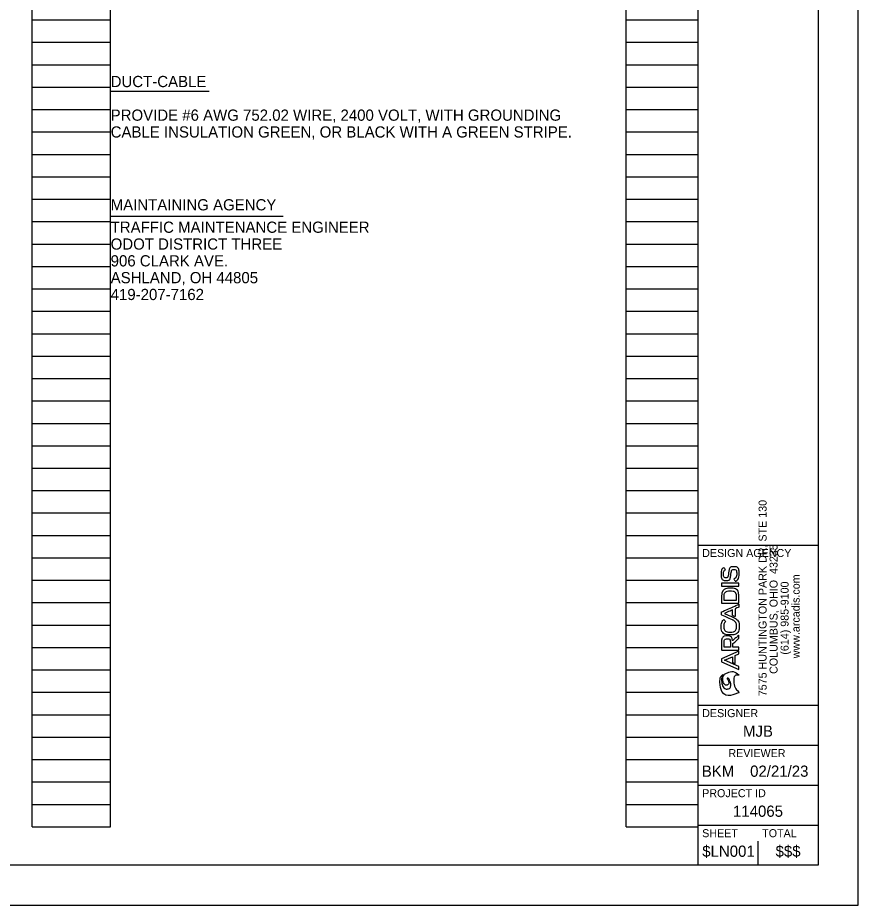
# Model space of a CAD drawing. Extents: x 0 to 59.1, y 0 to 22.
# Drawn here: x 23.5 to 34, y 0 to 11.09 of the extents above; entities that cross this region are included whole.
import ezdxf

# ---------------------------------------------------------------- set-up
doc = ezdxf.new("R2010")
doc.units = 0
for name, color, linetype in [('SH_Border', 7, 'Continuous'), ('SH_Cut_Line', 7, 'Continuous'), ('SH_Data', 7, 'Continuous'), ('SH_Text', 7, 'Continuous')]:
    doc.layers.add(name, color=color, linetype=linetype)

msp = doc.modelspace()

# ---------------------------------------------------------------- linework, layer by layer
at = {"layer": 'SH_Border'}
for p, q in [((32, 0.5), (32, 21.5)), ((32, 4.5), (33.5, 4.5)), ((32, 2.5), (33.5, 2.5)), ((32, 2), (33.5, 2)), ((32, 1.5), (33.5, 1.5)), ((32, 1), (33.5, 1))]:
    msp.add_line(p, q, dxfattribs=at)
msp.add_lwpolyline([(1.5, 21.5), (33.5, 21.5), (33.5, 0.5), (1.5, 0.5)], close=True, dxfattribs=at)
at = {"layer": 'SH_Cut_Line'}
msp.add_lwpolyline([(0, 0), (34, 0), (34, 22), (0, 22)], close=True, dxfattribs=at)
at = {"layer": 'SH_Data'}
for p, q in [((23.68, 0.98), (23.68, 21.14)), ((24.66, 0.98), (24.66, 21.14)), ((31.1, 0.98), (31.1, 21.14)), ((32, 0.98), (32, 21.14)), ((23.68, 11.06), (24.66, 11.06)), ((31.1, 11.06), (32, 11.06)), ((23.68, 10.78), (24.66, 10.78)), ((31.1, 10.78), (32, 10.78)), ((23.68, 10.5), (24.66, 10.5)), ((31.1, 10.5), (32, 10.5)), ((23.68, 10.22), (24.66, 10.22)), ((31.1, 10.22), (32, 10.22)), ((23.68, 9.94), (24.66, 9.94)), ((31.1, 9.94), (32, 9.94)), ((23.68, 9.66), (24.66, 9.66)), ((31.1, 9.66), (32, 9.66)), ((23.68, 9.38), (24.66, 9.38)), ((31.1, 9.38), (32, 9.38)), ((23.68, 9.1), (24.66, 9.1)), ((31.1, 9.1), (32, 9.1)), ((23.68, 8.82), (24.66, 8.82)), ((31.1, 8.82), (32, 8.82)), ((23.68, 8.54), (24.66, 8.54)), ((31.1, 8.54), (32, 8.54)), ((23.68, 8.26), (24.66, 8.26)), ((31.1, 8.26), (32, 8.26)), ((23.68, 7.98), (24.66, 7.98)), ((31.1, 7.98), (32, 7.98)), ((23.68, 7.7), (24.66, 7.7)), ((31.1, 7.7), (32, 7.7)), ((23.68, 7.42), (24.66, 7.42)), ((31.1, 7.42), (32, 7.42)), ((23.68, 7.14), (24.66, 7.14)), ((31.1, 7.14), (32, 7.14)), ((23.68, 6.86), (24.66, 6.86)), ((31.1, 6.86), (32, 6.86)), ((23.68, 6.58), (24.66, 6.58)), ((31.1, 6.58), (32, 6.58)), ((23.68, 6.3), (24.66, 6.3)), ((31.1, 6.3), (32, 6.3)), ((23.68, 6.02), (24.66, 6.02)), ((31.1, 6.02), (32, 6.02)), ((23.68, 5.74), (24.66, 5.74)), ((31.1, 5.74), (32, 5.74)), ((23.68, 5.46), (24.66, 5.46)), ((31.1, 5.46), (32, 5.46)), ((23.68, 5.18), (24.66, 5.18)), ((31.1, 5.18), (32, 5.18)), ((23.68, 4.9), (24.66, 4.9)), ((31.1, 4.9), (32, 4.9)), ((23.68, 4.62), (24.66, 4.62)), ((31.1, 4.62), (32, 4.62)), ((23.68, 4.34), (24.66, 4.34)), ((31.1, 4.34), (32, 4.34)), ((23.68, 4.06), (24.66, 4.06)), ((31.1, 4.06), (32, 4.06)), ((32.507, 4.022), (32.292, 4.022)), ((32.292, 4.022), (32.292, 3.988)), ((32.507, 4.022), (32.292, 4.022)), ((32.292, 4.022), (32.292, 3.988)), ((32.507, 4.022), (32.292, 4.022)), ((32.292, 4.022), (32.292, 3.988)), ((32.507, 3.988), (32.507, 4.022)), ((32.507, 3.988), (32.507, 4.022)), ((32.507, 3.988), (32.507, 4.022)), ((32.292, 3.988), (32.507, 3.988)), ((32.292, 3.988), (32.507, 3.988)), ((32.292, 3.988), (32.507, 3.988)), ((23.68, 3.78), (24.66, 3.78)), ((31.1, 3.78), (32, 3.78)), ((23.68, 3.5), (24.66, 3.5)), ((31.1, 3.5), (32, 3.5)), ((32.75, 3.5), (32.75, 3.5)), ((32.75, 3.5), (32.75, 3.5)), ((32.75, 3.5), (32.75, 3.5)), ((32.75, 3.5), (32.75, 3.5)), ((23.68, 3.22), (24.66, 3.22)), ((31.1, 3.22), (32, 3.22)), ((32.507, 3.175), (32.292, 3.079)), ((32.507, 3.175), (32.292, 3.079)), ((32.507, 3.175), (32.292, 3.079)), ((32.328, 3.06), (32.431, 3.105)), ((32.328, 3.06), (32.431, 3.105)), ((32.328, 3.06), (32.431, 3.105)), ((32.431, 3.105), (32.431, 3.034)), ((32.431, 3.105), (32.431, 3.034)), ((32.431, 3.105), (32.431, 3.034)), ((32.462, 3.119), (32.507, 3.139)), ((32.462, 3.119), (32.507, 3.139)), ((32.462, 3.119), (32.507, 3.139)), ((32.462, 3.02), (32.462, 3.119)), ((32.462, 3.02), (32.462, 3.119)), ((32.462, 3.02), (32.462, 3.119)), ((32.507, 3.139), (32.507, 3.175)), ((32.507, 3.139), (32.507, 3.175)), ((32.507, 3.139), (32.507, 3.175)), ((32.292, 3.079), (32.292, 3.041)), ((32.292, 3.079), (32.292, 3.041)), ((32.292, 3.079), (32.292, 3.041)), ((32.292, 3.041), (32.507, 2.945)), ((32.292, 3.041), (32.507, 2.945)), ((32.292, 3.041), (32.507, 2.945)), ((32.507, 2.981), (32.328, 3.06)), ((32.507, 2.981), (32.328, 3.06)), ((32.507, 2.981), (32.328, 3.06)), ((32.431, 3.034), (32.462, 3.02)), ((32.431, 3.034), (32.462, 3.02)), ((32.431, 3.034), (32.462, 3.02)), ((23.68, 2.94), (24.66, 2.94)), ((31.1, 2.94), (32, 2.94)), ((32.507, 2.945), (32.507, 2.981)), ((32.507, 2.945), (32.507, 2.981)), ((32.507, 2.945), (32.507, 2.981)), ((23.68, 2.66), (24.66, 2.66)), ((31.1, 2.66), (32, 2.66)), ((23.68, 2.38), (24.66, 2.38)), ((31.1, 2.38), (32, 2.38)), ((23.68, 2.1), (24.66, 2.1)), ((31.1, 2.1), (32, 2.1)), ((23.68, 1.82), (24.66, 1.82)), ((31.1, 1.82), (32, 1.82)), ((23.68, 1.54), (24.66, 1.54)), ((31.1, 1.54), (32, 1.54)), ((23.68, 1.26), (24.66, 1.26)), ((31.1, 1.26), (32, 1.26)), ((23.68, 0.98), (24.66, 0.98)), ((31.1, 0.98), (32, 0.98)), ((32.75, 0.5), (32.75, 0.8)), ((32.375, 0.675), (32.375, 0.675))]:
    msp.add_line(p, q, dxfattribs=at)
for points, degree in [([(32.34, 4.193), (32.325, 4.183), (32.316, 4.163), (32.316, 4.14), (32.316, 4.111), (32.328, 4.09), (32.348, 4.09), (32.369, 4.09), (32.375, 4.114), (32.379, 4.143), (32.385, 4.187), (32.398, 4.229), (32.446, 4.229), (32.494, 4.229), (32.512, 4.185), (32.512, 4.14), (32.512, 4.099), (32.5, 4.067), (32.463, 4.047), (32.463, 4.047), (32.446, 4.073), (32.446, 4.073), (32.472, 4.088), (32.482, 4.115), (32.482, 4.14), (32.482, 4.166), (32.473, 4.195), (32.446, 4.195), (32.422, 4.195), (32.414, 4.17), (32.41, 4.14), (32.405, 4.097), (32.394, 4.056), (32.348, 4.056), (32.303, 4.056), (32.286, 4.1), (32.286, 4.139), (32.286, 4.17), (32.293, 4.201), (32.322, 4.22), (32.322, 4.22), (32.34, 4.193), (32.34, 4.193), (32.34, 4.193), (32.34, 4.193), (32.34, 4.193)], 3), ([(32.34, 4.193), (32.325, 4.183), (32.316, 4.163), (32.316, 4.14), (32.316, 4.111), (32.328, 4.09), (32.348, 4.09), (32.369, 4.09), (32.375, 4.114), (32.379, 4.143), (32.385, 4.187), (32.398, 4.229), (32.446, 4.229), (32.494, 4.229), (32.512, 4.185), (32.512, 4.14), (32.512, 4.099), (32.5, 4.067), (32.463, 4.047), (32.463, 4.047), (32.446, 4.073), (32.446, 4.073), (32.472, 4.088), (32.482, 4.115), (32.482, 4.14), (32.482, 4.166), (32.473, 4.195), (32.446, 4.195), (32.422, 4.195), (32.414, 4.17), (32.41, 4.14), (32.405, 4.097), (32.394, 4.056), (32.348, 4.056), (32.303, 4.056), (32.286, 4.1), (32.286, 4.139), (32.286, 4.17), (32.293, 4.201), (32.322, 4.22), (32.322, 4.22), (32.34, 4.193), (32.34, 4.193), (32.34, 4.193), (32.34, 4.193), (32.34, 4.193)], 3), ([(32.34, 4.193), (32.325, 4.183), (32.316, 4.163), (32.316, 4.14), (32.316, 4.111), (32.328, 4.09), (32.348, 4.09), (32.369, 4.09), (32.375, 4.114), (32.379, 4.143), (32.385, 4.187), (32.398, 4.229), (32.446, 4.229), (32.494, 4.229), (32.512, 4.185), (32.512, 4.14), (32.512, 4.099), (32.5, 4.067), (32.463, 4.047), (32.463, 4.047), (32.446, 4.073), (32.446, 4.073), (32.472, 4.088), (32.482, 4.115), (32.482, 4.14), (32.482, 4.166), (32.473, 4.195), (32.446, 4.195), (32.422, 4.195), (32.414, 4.17), (32.41, 4.14), (32.405, 4.097), (32.394, 4.056), (32.348, 4.056), (32.303, 4.056), (32.286, 4.1), (32.286, 4.139), (32.286, 4.17), (32.293, 4.201), (32.322, 4.22), (32.322, 4.22), (32.34, 4.193), (32.34, 4.193), (32.34, 4.193), (32.34, 4.193), (32.34, 4.193)], 3), ([(32.292, 3.772), (32.292, 3.772), (32.507, 3.772), (32.507, 3.772), (32.507, 3.772), (32.507, 3.854), (32.507, 3.854), (32.507, 3.929), (32.452, 3.963), (32.398, 3.962), (32.345, 3.961), (32.292, 3.927), (32.292, 3.854)], 3), ([(32.292, 3.772), (32.292, 3.772), (32.507, 3.772), (32.507, 3.772), (32.507, 3.772), (32.507, 3.854), (32.507, 3.854), (32.507, 3.929), (32.452, 3.963), (32.398, 3.962), (32.345, 3.961), (32.292, 3.927), (32.292, 3.854)], 3), ([(32.292, 3.772), (32.292, 3.772), (32.507, 3.772), (32.507, 3.772), (32.507, 3.772), (32.507, 3.854), (32.507, 3.854), (32.507, 3.929), (32.452, 3.963), (32.398, 3.962), (32.345, 3.961), (32.292, 3.927), (32.292, 3.854)], 3), ([(32.325, 3.806), (32.325, 3.806), (32.325, 3.854), (32.325, 3.854), (32.325, 3.905), (32.361, 3.927), (32.398, 3.928), (32.435, 3.929), (32.474, 3.906), (32.474, 3.854), (32.474, 3.854), (32.474, 3.806), (32.474, 3.806)], 3), ([(32.325, 3.806), (32.325, 3.806), (32.325, 3.854), (32.325, 3.854), (32.325, 3.905), (32.361, 3.927), (32.398, 3.928), (32.435, 3.929), (32.474, 3.906), (32.474, 3.854), (32.474, 3.854), (32.474, 3.806), (32.474, 3.806)], 3), ([(32.325, 3.806), (32.325, 3.806), (32.325, 3.854), (32.325, 3.854), (32.325, 3.905), (32.361, 3.927), (32.398, 3.928), (32.435, 3.929), (32.474, 3.906), (32.474, 3.854), (32.474, 3.854), (32.474, 3.806), (32.474, 3.806)], 3), ([(32.292, 3.854), (32.292, 3.854), (32.292, 3.772), (32.292, 3.772)], 2), ([(32.292, 3.854), (32.292, 3.854), (32.292, 3.772), (32.292, 3.772)], 2), ([(32.292, 3.854), (32.292, 3.854), (32.292, 3.772), (32.292, 3.772)], 2), ([(32.474, 3.806), (32.474, 3.806), (32.325, 3.806), (32.325, 3.806)], 2), ([(32.474, 3.806), (32.474, 3.806), (32.325, 3.806), (32.325, 3.806)], 2), ([(32.474, 3.806), (32.474, 3.806), (32.325, 3.806), (32.325, 3.806)], 2), ([(32.292, 3.664), (32.292, 3.664), (32.292, 3.626), (32.292, 3.626), (32.292, 3.626), (32.432, 3.563), (32.432, 3.563), (32.432, 3.563), (32.432, 3.563), (32.432, 3.563), (32.445, 3.557), (32.453, 3.549), (32.456, 3.547), (32.471, 3.532), (32.479, 3.51), (32.479, 3.49), (32.479, 3.434), (32.44, 3.411), (32.401, 3.41), (32.361, 3.41), (32.321, 3.435), (32.321, 3.49), (32.321, 3.51), (32.328, 3.53), (32.343, 3.545), (32.343, 3.545), (32.321, 3.569), (32.321, 3.569), (32.299, 3.547), (32.288, 3.519), (32.288, 3.49), (32.288, 3.413), (32.345, 3.376), (32.401, 3.376), (32.458, 3.376), (32.512, 3.412), (32.512, 3.49), (32.512, 3.52), (32.502, 3.549), (32.48, 3.571), (32.48, 3.571), (32.466, 3.584), (32.446, 3.593), (32.446, 3.593), (32.44, 3.596), (32.44, 3.596), (32.44, 3.596), (32.425, 3.602), (32.425, 3.602), (32.425, 3.602), (32.425, 3.602), (32.425, 3.602), (32.425, 3.602), (32.328, 3.645), (32.328, 3.645), (32.328, 3.645), (32.431, 3.69), (32.431, 3.69), (32.431, 3.69), (32.431, 3.619), (32.431, 3.619), (32.431, 3.619), (32.462, 3.605), (32.462, 3.605), (32.462, 3.605), (32.462, 3.704), (32.462, 3.704), (32.462, 3.704), (32.507, 3.724), (32.507, 3.724), (32.507, 3.724), (32.507, 3.76), (32.507, 3.76), (32.507, 3.76), (32.292, 3.664), (32.292, 3.664), (32.292, 3.664), (32.292, 3.664), (32.292, 3.664)], 3), ([(32.292, 3.664), (32.292, 3.664), (32.292, 3.626), (32.292, 3.626), (32.292, 3.626), (32.432, 3.563), (32.432, 3.563), (32.432, 3.563), (32.432, 3.563), (32.432, 3.563), (32.445, 3.557), (32.453, 3.549), (32.456, 3.547), (32.471, 3.532), (32.479, 3.51), (32.479, 3.49), (32.479, 3.434), (32.44, 3.411), (32.401, 3.41), (32.361, 3.41), (32.321, 3.435), (32.321, 3.49), (32.321, 3.51), (32.328, 3.53), (32.343, 3.545), (32.343, 3.545), (32.321, 3.569), (32.321, 3.569), (32.299, 3.547), (32.288, 3.519), (32.288, 3.49), (32.288, 3.413), (32.345, 3.376), (32.401, 3.376), (32.458, 3.376), (32.512, 3.412), (32.512, 3.49), (32.512, 3.52), (32.502, 3.549), (32.48, 3.571), (32.48, 3.571), (32.466, 3.584), (32.446, 3.593), (32.446, 3.593), (32.44, 3.596), (32.44, 3.596), (32.44, 3.596), (32.425, 3.602), (32.425, 3.602), (32.425, 3.602), (32.425, 3.602), (32.425, 3.602), (32.425, 3.602), (32.328, 3.645), (32.328, 3.645), (32.328, 3.645), (32.431, 3.69), (32.431, 3.69), (32.431, 3.69), (32.431, 3.619), (32.431, 3.619), (32.431, 3.619), (32.462, 3.605), (32.462, 3.605), (32.462, 3.605), (32.462, 3.704), (32.462, 3.704), (32.462, 3.704), (32.507, 3.724), (32.507, 3.724), (32.507, 3.724), (32.507, 3.76), (32.507, 3.76), (32.507, 3.76), (32.292, 3.664), (32.292, 3.664), (32.292, 3.664), (32.292, 3.664), (32.292, 3.664)], 3), ([(32.292, 3.664), (32.292, 3.664), (32.292, 3.626), (32.292, 3.626), (32.292, 3.626), (32.432, 3.563), (32.432, 3.563), (32.432, 3.563), (32.432, 3.563), (32.432, 3.563), (32.445, 3.557), (32.453, 3.549), (32.456, 3.547), (32.471, 3.532), (32.479, 3.51), (32.479, 3.49), (32.479, 3.434), (32.44, 3.411), (32.401, 3.41), (32.361, 3.41), (32.321, 3.435), (32.321, 3.49), (32.321, 3.51), (32.328, 3.53), (32.343, 3.545), (32.343, 3.545), (32.321, 3.569), (32.321, 3.569), (32.299, 3.547), (32.288, 3.519), (32.288, 3.49), (32.288, 3.413), (32.345, 3.376), (32.401, 3.376), (32.458, 3.376), (32.512, 3.412), (32.512, 3.49), (32.512, 3.52), (32.502, 3.549), (32.48, 3.571), (32.48, 3.571), (32.466, 3.584), (32.446, 3.593), (32.446, 3.593), (32.44, 3.596), (32.44, 3.596), (32.44, 3.596), (32.425, 3.602), (32.425, 3.602), (32.425, 3.602), (32.425, 3.602), (32.425, 3.602), (32.425, 3.602), (32.328, 3.645), (32.328, 3.645), (32.328, 3.645), (32.431, 3.69), (32.431, 3.69), (32.431, 3.69), (32.431, 3.619), (32.431, 3.619), (32.431, 3.619), (32.462, 3.605), (32.462, 3.605), (32.462, 3.605), (32.462, 3.704), (32.462, 3.704), (32.462, 3.704), (32.507, 3.724), (32.507, 3.724), (32.507, 3.724), (32.507, 3.76), (32.507, 3.76), (32.507, 3.76), (32.292, 3.664), (32.292, 3.664), (32.292, 3.664), (32.292, 3.664), (32.292, 3.664)], 3), ([(32.43, 3.305), (32.423, 3.348), (32.393, 3.364), (32.362, 3.364), (32.326, 3.364), (32.292, 3.337), (32.292, 3.288), (32.292, 3.254), (32.292, 3.221), (32.292, 3.187), (32.292, 3.187), (32.507, 3.187), (32.507, 3.187), (32.507, 3.187), (32.507, 3.222), (32.507, 3.222), (32.507, 3.222), (32.433, 3.222), (32.433, 3.222), (32.433, 3.222), (32.433, 3.267), (32.433, 3.267), (32.433, 3.267), (32.507, 3.333), (32.507, 3.333), (32.507, 3.333), (32.507, 3.373), (32.507, 3.373)], 3), ([(32.43, 3.305), (32.423, 3.348), (32.393, 3.364), (32.362, 3.364), (32.326, 3.364), (32.292, 3.337), (32.292, 3.288), (32.292, 3.254), (32.292, 3.221), (32.292, 3.187), (32.292, 3.187), (32.507, 3.187), (32.507, 3.187), (32.507, 3.187), (32.507, 3.222), (32.507, 3.222), (32.507, 3.222), (32.433, 3.222), (32.433, 3.222), (32.433, 3.222), (32.433, 3.267), (32.433, 3.267), (32.433, 3.267), (32.507, 3.333), (32.507, 3.333), (32.507, 3.333), (32.507, 3.373), (32.507, 3.373)], 3), ([(32.43, 3.305), (32.423, 3.348), (32.393, 3.364), (32.362, 3.364), (32.326, 3.364), (32.292, 3.337), (32.292, 3.288), (32.292, 3.254), (32.292, 3.221), (32.292, 3.187), (32.292, 3.187), (32.507, 3.187), (32.507, 3.187), (32.507, 3.187), (32.507, 3.222), (32.507, 3.222), (32.507, 3.222), (32.433, 3.222), (32.433, 3.222), (32.433, 3.222), (32.433, 3.267), (32.433, 3.267), (32.433, 3.267), (32.507, 3.333), (32.507, 3.333), (32.507, 3.333), (32.507, 3.373), (32.507, 3.373)], 3), ([(32.323, 3.288), (32.323, 3.316), (32.344, 3.329), (32.363, 3.329), (32.383, 3.329), (32.402, 3.316), (32.402, 3.287), (32.402, 3.287), (32.402, 3.222), (32.402, 3.222), (32.402, 3.222), (32.323, 3.222), (32.323, 3.222)], 3), ([(32.323, 3.288), (32.323, 3.316), (32.344, 3.329), (32.363, 3.329), (32.383, 3.329), (32.402, 3.316), (32.402, 3.287), (32.402, 3.287), (32.402, 3.222), (32.402, 3.222), (32.402, 3.222), (32.323, 3.222), (32.323, 3.222)], 3), ([(32.323, 3.288), (32.323, 3.316), (32.344, 3.329), (32.363, 3.329), (32.383, 3.329), (32.402, 3.316), (32.402, 3.287), (32.402, 3.287), (32.402, 3.222), (32.402, 3.222), (32.402, 3.222), (32.323, 3.222), (32.323, 3.222)], 3), ([(32.507, 3.373), (32.507, 3.373), (32.43, 3.305), (32.43, 3.305)], 2), ([(32.507, 3.373), (32.507, 3.373), (32.43, 3.305), (32.43, 3.305)], 2), ([(32.507, 3.373), (32.507, 3.373), (32.43, 3.305), (32.43, 3.305)], 2), ([(32.323, 3.222), (32.323, 3.222), (32.323, 3.288), (32.323, 3.288)], 2), ([(32.323, 3.222), (32.323, 3.222), (32.323, 3.288), (32.323, 3.288)], 2), ([(32.323, 3.222), (32.323, 3.222), (32.323, 3.288), (32.323, 3.288)], 2), ([(32.272, 2.786), (32.282, 2.575), (32.514, 2.656), (32.514, 2.656), (32.494, 2.674), (32.446, 2.734), (32.446, 2.817), (32.446, 2.817), (32.446, 2.817), (32.446, 2.818), (32.446, 2.858), (32.48, 2.881), (32.514, 2.872), (32.514, 2.872), (32.441, 2.935), (32.357, 2.9), (32.329, 2.888), (32.309, 2.857), (32.309, 2.821), (32.309, 2.808), (32.311, 2.795), (32.316, 2.782), (32.329, 2.752), (32.356, 2.748), (32.369, 2.754), (32.378, 2.759), (32.383, 2.768), (32.383, 2.777), (32.383, 2.779), (32.383, 2.781), (32.383, 2.782), (32.378, 2.813), (32.364, 2.826), (32.364, 2.833), (32.364, 2.834), (32.364, 2.835), (32.365, 2.835), (32.368, 2.84), (32.383, 2.836), (32.398, 2.796), (32.402, 2.787), (32.407, 2.769), (32.407, 2.752), (32.407, 2.732), (32.401, 2.712), (32.38, 2.706), (32.343, 2.693), (32.298, 2.738), (32.293, 2.804), (32.292, 2.807), (32.292, 2.812), (32.292, 2.815), (32.292, 2.849), (32.307, 2.873), (32.317, 2.885), (32.294, 2.871), (32.273, 2.842), (32.272, 2.796), (32.272, 2.796), (32.272, 2.792), (32.272, 2.786), (32.272, 2.786), (32.272, 2.786), (32.272, 2.786)], 3), ([(32.272, 2.786), (32.282, 2.575), (32.514, 2.656), (32.514, 2.656), (32.494, 2.674), (32.446, 2.734), (32.446, 2.817), (32.446, 2.817), (32.446, 2.817), (32.446, 2.818), (32.446, 2.858), (32.48, 2.881), (32.514, 2.872), (32.514, 2.872), (32.441, 2.935), (32.357, 2.9), (32.329, 2.888), (32.309, 2.857), (32.309, 2.821), (32.309, 2.808), (32.311, 2.795), (32.316, 2.782), (32.329, 2.752), (32.356, 2.748), (32.369, 2.754), (32.378, 2.759), (32.383, 2.768), (32.383, 2.777), (32.383, 2.779), (32.383, 2.781), (32.383, 2.782), (32.378, 2.813), (32.364, 2.826), (32.364, 2.833), (32.364, 2.834), (32.364, 2.835), (32.365, 2.835), (32.368, 2.84), (32.383, 2.836), (32.398, 2.796), (32.402, 2.787), (32.407, 2.769), (32.407, 2.752), (32.407, 2.732), (32.401, 2.712), (32.38, 2.706), (32.343, 2.693), (32.298, 2.738), (32.293, 2.804), (32.292, 2.807), (32.292, 2.812), (32.292, 2.815), (32.292, 2.849), (32.307, 2.873), (32.317, 2.885), (32.294, 2.871), (32.273, 2.842), (32.272, 2.796), (32.272, 2.796), (32.272, 2.792), (32.272, 2.786), (32.272, 2.786), (32.272, 2.786), (32.272, 2.786)], 3), ([(32.272, 2.786), (32.282, 2.575), (32.514, 2.656), (32.514, 2.656), (32.494, 2.674), (32.446, 2.734), (32.446, 2.817), (32.446, 2.817), (32.446, 2.817), (32.446, 2.818), (32.446, 2.858), (32.48, 2.881), (32.514, 2.872), (32.514, 2.872), (32.441, 2.935), (32.357, 2.9), (32.329, 2.888), (32.309, 2.857), (32.309, 2.821), (32.309, 2.808), (32.311, 2.795), (32.316, 2.782), (32.329, 2.752), (32.356, 2.748), (32.369, 2.754), (32.378, 2.759), (32.383, 2.768), (32.383, 2.777), (32.383, 2.779), (32.383, 2.781), (32.383, 2.782), (32.378, 2.813), (32.364, 2.826), (32.364, 2.833), (32.364, 2.834), (32.364, 2.835), (32.365, 2.835), (32.368, 2.84), (32.383, 2.836), (32.398, 2.796), (32.402, 2.787), (32.407, 2.769), (32.407, 2.752), (32.407, 2.732), (32.401, 2.712), (32.38, 2.706), (32.343, 2.693), (32.298, 2.738), (32.293, 2.804), (32.292, 2.807), (32.292, 2.812), (32.292, 2.815), (32.292, 2.849), (32.307, 2.873), (32.317, 2.885), (32.294, 2.871), (32.273, 2.842), (32.272, 2.796), (32.272, 2.796), (32.272, 2.792), (32.272, 2.786), (32.272, 2.786), (32.272, 2.786), (32.272, 2.786)], 3)]:
    msp.add_open_spline(points, degree=degree, dxfattribs=at)
at = {"layer": 'SH_Text'}
for p, q in [((24.66, 10.171), (25.889, 10.171)), ((24.662, 8.606), (26.816, 8.606))]:
    msp.add_line(p, q, dxfattribs=at)

# ---------------------------------------------------------------- texts
at = {"layer": 'SH_Data'}
for s, p in [('7575 HUNTINGTON PARK DR, STE 130', (32.855, 2.611)), ('7575 HUNTINGTON PARK DR, STE 130', (32.855, 2.611)), ('7575 HUNTINGTON PARK DR, STE 130', (32.855, 2.611)), ('COLUMBUS, OHIO  43235', (32.992, 2.89)), ('COLUMBUS, OHIO  43235', (32.992, 2.89)), ('COLUMBUS, OHIO  43235', (32.992, 2.89)), ('www.arcadis.com', (33.268, 3.085)), ('www.arcadis.com', (33.268, 3.085)), ('www.arcadis.com', (33.268, 3.085)), ('(614) 985-9100', (33.13, 3.13)), ('(614) 985-9100', (33.13, 3.13)), ('(614) 985-9100', (33.13, 3.13))]:
    msp.add_text(s, height=0.1, rotation=90, dxfattribs=at).set_placement(p)
for s, height, p in [('DESIGN AGENCY', 0.1, (32.05, 4.35)), ('DESIGNER', 0.1, (32.05, 2.35)), ('MJB', 0.14, (32.56, 2.105)), ('REVIEWER', 0.1, (32.378, 1.85)), ('BKM', 0.14, (32.045, 1.605)), ('02/21/23', 0.14, (32.649, 1.605)), ('PROJECT ID', 0.1, (32.05, 1.35)), ('114065', 0.14, (32.435, 1.105)), ('SHEET', 0.1, (32.05, 0.85)), ('TOTAL', 0.1, (32.8, 0.85)), ('$LN001', 0.14, (32.051, 0.605)), ('$$$', 0.14, (32.967, 0.605))]:
    msp.add_text(s, height=height, dxfattribs=at).set_placement(p)
at = {"layer": 'SH_Text'}
for s, p in [('DUCT-CABLE', (24.66, 10.22)), ('PROVIDE #6 AWG 752.02 WIRE, 2400 VOLT, WITH GROUNDING ', (24.66, 9.8)), ('CABLE INSULATION GREEN, OR BLACK WITH A GREEN STRIPE.', (24.66, 9.59)), ('MAINTAINING AGENCY', (24.66, 8.68)), ('TRAFFIC MAINTENANCE ENGINEER', (24.66, 8.4)), ('ODOT DISTRICT THREE', (24.66, 8.19)), ('906 CLARK AVE.', (24.66, 7.98)), ('ASHLAND, OH 44805', (24.66, 7.77)), ('419-207-7162', (24.66, 7.56))]:
    msp.add_text(s, height=0.14, dxfattribs=at).set_placement(p)

doc.saveas('drawing.dxf')
